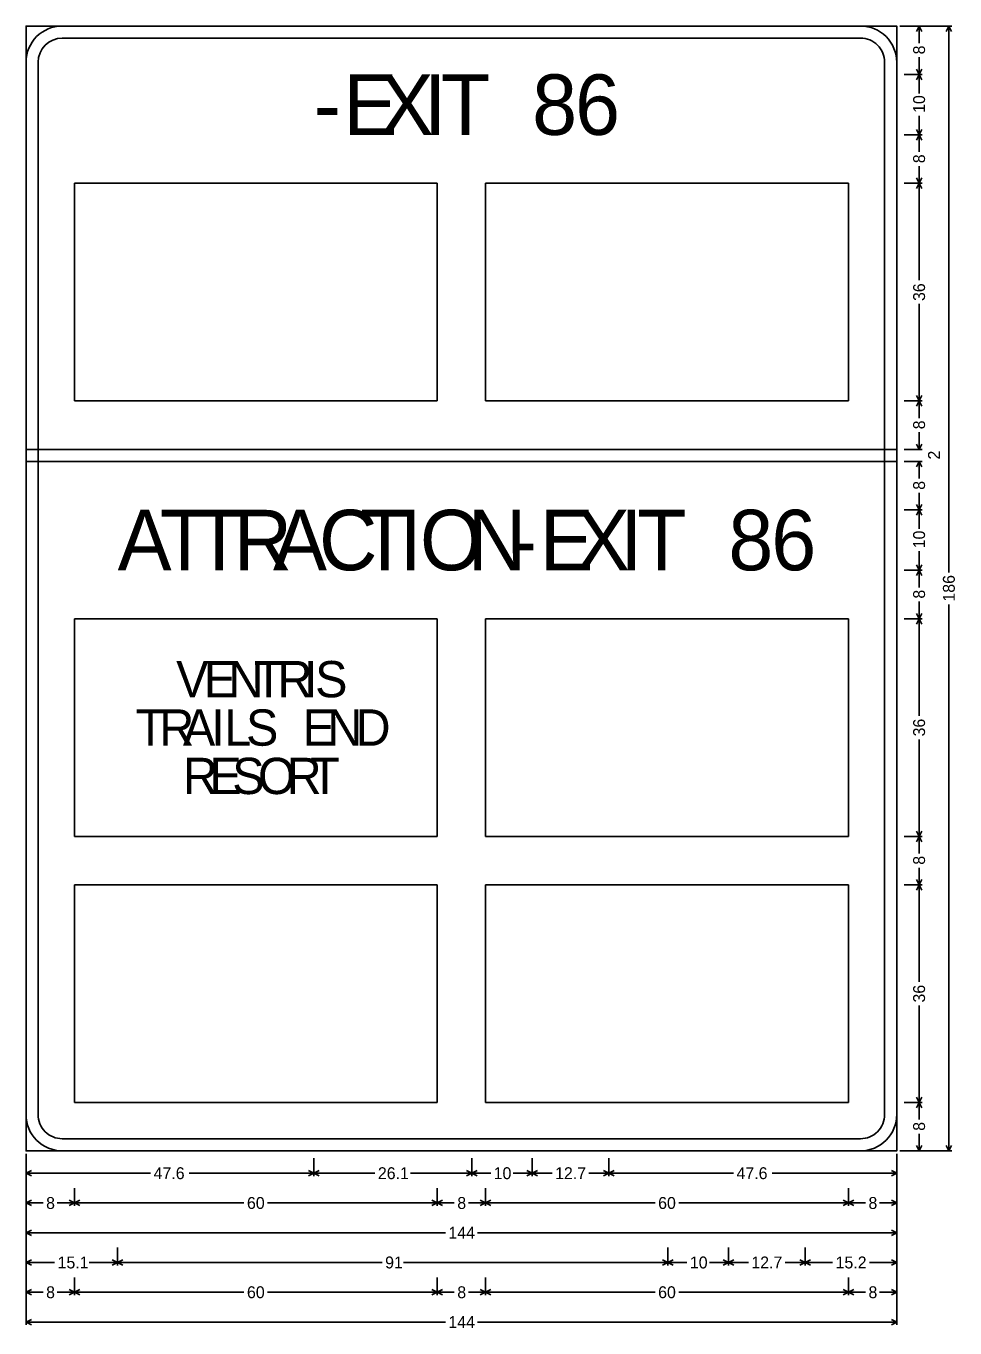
# Model space of a CAD drawing. Extents: x 667331 to 731245, y 738830 to 753817.
# Drawn here: x 729776.8 to 730053.4, y 747199.1 to 747586.6 of the extents above; entities that cross this region are included whole.
import ezdxf

# ---------------------------------------------------------------- set-up
doc = ezdxf.new("R2010")
doc.units = 0
doc.layers.add('R_SIGN', color=7, linetype='Continuous')

msp = doc.modelspace()

# ---------------------------------------------------------------- linework, layer by layer
at = {"layer": 'R_SIGN'}
for p, q in [((730052.43, 747586.65), (730036.93, 747586.65)), ((730043.57, 747586.65), (730038.26, 747586.65)), ((730041.9, 747585.06), (730042.69, 747586.65)), ((730042.69, 747581.56), (730042.69, 747586.65)), ((730043.48, 747585.06), (730042.69, 747586.65)), ((730050.75, 747585.06), (730051.55, 747586.65)), ((730051.55, 747424.04), (730051.55, 747586.65)), ((730052.34, 747585.06), (730051.55, 747586.65)), ((730042.69, 747577.34), (730042.69, 747572.25)), ((730041.9, 747573.83), (730042.69, 747572.25)), ((730043.48, 747573.83), (730042.69, 747572.25)), ((730043.57, 747572.25), (730038.26, 747572.25)), ((730041.9, 747570.66), (730042.69, 747572.25)), ((730042.69, 747566.59), (730042.69, 747572.25)), ((730043.48, 747570.66), (730042.69, 747572.25)), ((730042.69, 747559.9), (730042.69, 747554.25)), ((730043.57, 747554.25), (730038.26, 747554.25)), ((730041.9, 747555.83), (730042.69, 747554.25)), ((730041.9, 747552.66), (730042.69, 747554.25)), ((730043.48, 747555.83), (730042.69, 747554.25)), ((730042.69, 747549.16), (730042.69, 747554.25)), ((730043.48, 747552.66), (730042.69, 747554.25)), ((730041.9, 747541.43), (730042.69, 747539.85)), ((730042.69, 747544.94), (730042.69, 747539.85)), ((730043.48, 747541.43), (730042.69, 747539.85)), ((729791.24, 747475.05), (729791.24, 747539.85)), ((729791.24, 747539.85), (729899.24, 747539.85)), ((729899.24, 747539.85), (729899.24, 747475.05)), ((729913.64, 747475.05), (729913.64, 747539.85)), ((729913.64, 747539.85), (730021.64, 747539.85)), ((730021.64, 747539.85), (730021.64, 747475.05)), ((730043.57, 747539.85), (730038.26, 747539.85)), ((730041.9, 747538.26), (730042.69, 747539.85)), ((730042.69, 747510.98), (730042.69, 747539.85)), ((730043.48, 747538.26), (730042.69, 747539.85)), ((730042.69, 747503.92), (730042.69, 747475.05)), ((730041.9, 747476.63), (730042.69, 747475.05)), ((730043.48, 747476.63), (730042.69, 747475.05)), ((729899.24, 747475.05), (729791.24, 747475.05)), ((730021.64, 747475.05), (729913.64, 747475.05)), ((730043.57, 747475.05), (730038.26, 747475.05)), ((730041.9, 747473.46), (730042.69, 747475.05)), ((730042.69, 747469.96), (730042.69, 747475.05)), ((730043.48, 747473.46), (730042.69, 747475.05)), ((730042.69, 747465.74), (730042.69, 747460.65)), ((730043.57, 747460.65), (730038.26, 747460.65)), ((730041.9, 747462.23), (730042.69, 747460.65)), ((730043.48, 747462.23), (730042.69, 747460.65)), ((730043.57, 747457.05), (730038.26, 747457.05)), ((730041.9, 747455.46), (730042.69, 747457.05)), ((730042.69, 747451.96), (730042.69, 747457.05)), ((730043.48, 747455.46), (730042.69, 747457.05)), ((730042.69, 747447.74), (730042.69, 747442.65)), ((730043.57, 747442.65), (730038.26, 747442.65)), ((730041.9, 747444.23), (730042.69, 747442.65)), ((730041.9, 747441.06), (730042.69, 747442.65)), ((730043.48, 747444.23), (730042.69, 747442.65)), ((730042.69, 747436.99), (730042.69, 747442.65)), ((730043.48, 747441.06), (730042.69, 747442.65)), ((730042.69, 747430.3), (730042.69, 747424.65)), ((730041.9, 747426.23), (730042.69, 747424.65)), ((730043.48, 747426.23), (730042.69, 747424.65)), ((730043.57, 747424.65), (730038.26, 747424.65)), ((730041.9, 747423.06), (730042.69, 747424.65)), ((730042.69, 747419.56), (730042.69, 747424.65)), ((730043.48, 747423.06), (730042.69, 747424.65)), ((730042.69, 747415.34), (730042.69, 747410.25)), ((730051.55, 747414.45), (730051.55, 747251.85)), ((729791.24, 747345.45), (729791.24, 747410.25)), ((729791.24, 747410.25), (729899.24, 747410.25)), ((729899.24, 747410.25), (729899.24, 747345.45)), ((729913.64, 747345.45), (729913.64, 747410.25)), ((729913.64, 747410.25), (730021.64, 747410.25)), ((730021.64, 747410.25), (730021.64, 747345.45)), ((730043.57, 747410.25), (730038.26, 747410.25)), ((730041.9, 747411.83), (730042.69, 747410.25)), ((730041.9, 747408.66), (730042.69, 747410.25)), ((730043.48, 747411.83), (730042.69, 747410.25)), ((730042.69, 747381.38), (730042.69, 747410.25)), ((730043.48, 747408.66), (730042.69, 747410.25)), ((730042.69, 747374.32), (730042.69, 747345.45)), ((729899.24, 747345.45), (729791.24, 747345.45)), ((730021.64, 747345.45), (729913.64, 747345.45)), ((730043.57, 747345.45), (730038.26, 747345.45)), ((730041.9, 747347.03), (730042.69, 747345.45)), ((730041.9, 747343.86), (730042.69, 747345.45)), ((730043.48, 747347.03), (730042.69, 747345.45)), ((730042.69, 747340.36), (730042.69, 747345.45)), ((730043.48, 747343.86), (730042.69, 747345.45)), ((730042.69, 747336.14), (730042.69, 747331.05)), ((730041.9, 747332.63), (730042.69, 747331.05)), ((730043.48, 747332.63), (730042.69, 747331.05)), ((729791.24, 747266.25), (729791.24, 747331.05)), ((729791.24, 747331.05), (729899.24, 747331.05)), ((729899.24, 747331.05), (729899.24, 747266.25)), ((729913.64, 747266.25), (729913.64, 747331.05)), ((729913.64, 747331.05), (730021.64, 747331.05)), ((730021.64, 747331.05), (730021.64, 747266.25)), ((730043.57, 747331.05), (730038.26, 747331.05)), ((730041.9, 747329.46), (730042.69, 747331.05)), ((730042.69, 747302.18), (730042.69, 747331.05)), ((730043.48, 747329.46), (730042.69, 747331.05)), ((730042.69, 747295.12), (730042.69, 747266.25)), ((729899.24, 747266.25), (729791.24, 747266.25)), ((730021.64, 747266.25), (729913.64, 747266.25)), ((730043.57, 747266.25), (730038.26, 747266.25)), ((730043.57, 747266.25), (730038.26, 747266.25)), ((730041.9, 747267.83), (730042.69, 747266.25)), ((730041.9, 747264.66), (730042.69, 747266.25)), ((730043.48, 747267.83), (730042.69, 747266.25)), ((730042.69, 747261.16), (730042.69, 747266.25)), ((730043.48, 747264.66), (730042.69, 747266.25)), ((730042.69, 747256.94), (730042.69, 747251.85)), ((729776.84, 747200.03), (729776.84, 747250.96)), ((730036.04, 747200.03), (730036.04, 747250.96)), ((730052.43, 747251.85), (730036.93, 747251.85)), ((730043.57, 747251.85), (730038.26, 747251.85)), ((730041.9, 747253.43), (730042.69, 747251.85)), ((730043.48, 747253.43), (730042.69, 747251.85)), ((730050.75, 747253.43), (730051.55, 747251.85)), ((730052.34, 747253.43), (730051.55, 747251.85)), ((729776.84, 747244.32), (729776.84, 747249.63)), ((729862.52, 747244.32), (729862.52, 747249.63)), ((729909.5, 747244.32), (729909.5, 747249.63)), ((729927.5, 747244.32), (729927.5, 747249.63)), ((729950.36, 747244.32), (729950.36, 747249.63)), ((729950.36, 747244.32), (729950.36, 747249.63)), ((730036.04, 747244.32), (730036.04, 747249.63)), ((729778.43, 747245.99), (729776.84, 747245.2)), ((729813.94, 747245.2), (729776.84, 747245.2)), ((729778.43, 747244.41), (729776.84, 747245.2)), ((729825.43, 747245.2), (729862.52, 747245.2)), ((729860.94, 747245.99), (729862.52, 747245.2)), ((729860.94, 747244.41), (729862.52, 747245.2)), ((729864.11, 747245.99), (729862.52, 747245.2)), ((729880.7, 747245.2), (729862.52, 747245.2)), ((729864.11, 747244.41), (729862.52, 747245.2)), ((729891.33, 747245.2), (729909.5, 747245.2)), ((729907.92, 747245.99), (729909.5, 747245.2)), ((729907.92, 747244.41), (729909.5, 747245.2)), ((729911.09, 747245.99), (729909.5, 747245.2)), ((729915.16, 747245.2), (729909.5, 747245.2)), ((729911.09, 747244.41), (729909.5, 747245.2)), ((729921.85, 747245.2), (729927.5, 747245.2)), ((729925.92, 747245.99), (729927.5, 747245.2)), ((729925.92, 747244.41), (729927.5, 747245.2)), ((729929.09, 747245.99), (729927.5, 747245.2)), ((729933.46, 747245.2), (729927.5, 747245.2)), ((729929.09, 747244.41), (729927.5, 747245.2)), ((729944.41, 747245.2), (729950.36, 747245.2)), ((729948.78, 747245.99), (729950.36, 747245.2)), ((729948.78, 747244.41), (729950.36, 747245.2)), ((729951.95, 747245.99), (729950.36, 747245.2)), ((729987.46, 747245.2), (729950.36, 747245.2)), ((729951.95, 747244.41), (729950.36, 747245.2)), ((729998.95, 747245.2), (730036.04, 747245.2)), ((730034.46, 747245.99), (730036.04, 747245.2)), ((730034.46, 747244.41), (730036.04, 747245.2)), ((729776.84, 747235.46), (729776.84, 747240.77)), ((729791.24, 747235.46), (729791.24, 747240.77)), ((729899.24, 747235.46), (729899.24, 747240.77)), ((729913.64, 747235.46), (729913.64, 747240.77)), ((730021.64, 747235.46), (730021.64, 747240.77)), ((730021.64, 747235.46), (730021.64, 747240.77)), ((730036.04, 747235.46), (730036.04, 747240.77)), ((729778.43, 747237.14), (729776.84, 747236.34)), ((729781.93, 747236.34), (729776.84, 747236.34)), ((729778.43, 747235.55), (729776.84, 747236.34)), ((729786.15, 747236.34), (729791.24, 747236.34)), ((729789.66, 747237.14), (729791.24, 747236.34)), ((729789.66, 747235.55), (729791.24, 747236.34)), ((729792.83, 747237.14), (729791.24, 747236.34)), ((729841.72, 747236.34), (729791.24, 747236.34)), ((729792.83, 747235.55), (729791.24, 747236.34)), ((729848.77, 747236.34), (729899.24, 747236.34)), ((729897.66, 747237.14), (729899.24, 747236.34)), ((729897.66, 747235.55), (729899.24, 747236.34)), ((729900.83, 747237.14), (729899.24, 747236.34)), ((729904.33, 747236.34), (729899.24, 747236.34)), ((729900.83, 747235.55), (729899.24, 747236.34)), ((729908.55, 747236.34), (729913.64, 747236.34)), ((729912.06, 747237.14), (729913.64, 747236.34)), ((729912.06, 747235.55), (729913.64, 747236.34)), ((729915.23, 747237.14), (729913.64, 747236.34)), ((729964.12, 747236.34), (729913.64, 747236.34)), ((729915.23, 747235.55), (729913.64, 747236.34)), ((729971.17, 747236.34), (730021.64, 747236.34)), ((730020.06, 747237.14), (730021.64, 747236.34)), ((730020.06, 747235.55), (730021.64, 747236.34)), ((730023.23, 747237.14), (730021.64, 747236.34)), ((730026.73, 747236.34), (730021.64, 747236.34)), ((730023.23, 747235.55), (730021.64, 747236.34)), ((730030.95, 747236.34), (730036.04, 747236.34)), ((730034.46, 747237.14), (730036.04, 747236.34)), ((730034.46, 747235.55), (730036.04, 747236.34)), ((729776.84, 747226.6), (729776.84, 747231.91)), ((730036.04, 747226.6), (730036.04, 747231.91)), ((729778.43, 747228.28), (729776.84, 747227.49)), ((729901.69, 747227.49), (729776.84, 747227.49)), ((729778.43, 747226.69), (729776.84, 747227.49)), ((729911.2, 747227.49), (730036.04, 747227.49)), ((730034.46, 747228.28), (730036.04, 747227.49)), ((730034.46, 747226.69), (730036.04, 747227.49)), ((729776.84, 747217.74), (729776.84, 747223.06)), ((729804.11, 747217.74), (729804.11, 747223.06)), ((729967.91, 747217.74), (729967.91, 747223.06)), ((729985.91, 747217.74), (729985.91, 747223.06)), ((730008.77, 747217.74), (730008.77, 747223.06)), ((730008.77, 747217.74), (730008.77, 747223.06)), ((730036.04, 747217.74), (730036.04, 747223.06)), ((729778.43, 747219.42), (729776.84, 747218.63)), ((729785.35, 747218.63), (729776.84, 747218.63)), ((729778.43, 747217.83), (729776.84, 747218.63)), ((729795.6, 747218.63), (729804.11, 747218.63)), ((729802.53, 747219.42), (729804.11, 747218.63)), ((729802.53, 747217.83), (729804.11, 747218.63)), ((729805.7, 747219.42), (729804.11, 747218.63)), ((729882.86, 747218.63), (729804.11, 747218.63)), ((729805.7, 747217.83), (729804.11, 747218.63)), ((729889.17, 747218.63), (729967.91, 747218.63)), ((729966.33, 747219.42), (729967.91, 747218.63)), ((729966.33, 747217.83), (729967.91, 747218.63)), ((729969.5, 747219.42), (729967.91, 747218.63)), ((729973.57, 747218.63), (729967.91, 747218.63)), ((729969.5, 747217.83), (729967.91, 747218.63)), ((729980.26, 747218.63), (729985.91, 747218.63)), ((729984.33, 747219.42), (729985.91, 747218.63)), ((729984.33, 747217.83), (729985.91, 747218.63)), ((729987.5, 747219.42), (729985.91, 747218.63)), ((729991.87, 747218.63), (729985.91, 747218.63)), ((729987.5, 747217.83), (729985.91, 747218.63)), ((730002.82, 747218.63), (730008.77, 747218.63)), ((730007.19, 747219.42), (730008.77, 747218.63)), ((730007.19, 747217.83), (730008.77, 747218.63)), ((730010.36, 747219.42), (730008.77, 747218.63)), ((730016.94, 747218.63), (730008.77, 747218.63)), ((730010.36, 747217.83), (730008.77, 747218.63)), ((730027.88, 747218.63), (730036.04, 747218.63)), ((730034.46, 747219.42), (730036.04, 747218.63)), ((730034.46, 747217.83), (730036.04, 747218.63)), ((729776.84, 747208.88), (729776.84, 747214.2)), ((729791.24, 747208.88), (729791.24, 747214.2)), ((729899.24, 747208.88), (729899.24, 747214.2)), ((729913.64, 747208.88), (729913.64, 747214.2)), ((730021.64, 747208.88), (730021.64, 747214.2)), ((730021.64, 747208.88), (730021.64, 747214.2)), ((730036.04, 747208.88), (730036.04, 747214.2)), ((729778.43, 747210.56), (729776.84, 747209.77)), ((729781.93, 747209.77), (729776.84, 747209.77)), ((729778.43, 747208.98), (729776.84, 747209.77)), ((729786.15, 747209.77), (729791.24, 747209.77)), ((729789.66, 747210.56), (729791.24, 747209.77)), ((729789.66, 747208.98), (729791.24, 747209.77)), ((729792.83, 747210.56), (729791.24, 747209.77)), ((729841.72, 747209.77), (729791.24, 747209.77)), ((729792.83, 747208.98), (729791.24, 747209.77)), ((729848.77, 747209.77), (729899.24, 747209.77)), ((729897.66, 747210.56), (729899.24, 747209.77)), ((729897.66, 747208.98), (729899.24, 747209.77)), ((729900.83, 747210.56), (729899.24, 747209.77)), ((729904.33, 747209.77), (729899.24, 747209.77)), ((729900.83, 747208.98), (729899.24, 747209.77)), ((729908.55, 747209.77), (729913.64, 747209.77)), ((729912.06, 747210.56), (729913.64, 747209.77)), ((729912.06, 747208.98), (729913.64, 747209.77)), ((729915.23, 747210.56), (729913.64, 747209.77)), ((729964.12, 747209.77), (729913.64, 747209.77)), ((729915.23, 747208.98), (729913.64, 747209.77)), ((729971.17, 747209.77), (730021.64, 747209.77)), ((730020.06, 747210.56), (730021.64, 747209.77)), ((730020.06, 747208.98), (730021.64, 747209.77)), ((730023.23, 747210.56), (730021.64, 747209.77)), ((730026.73, 747209.77), (730021.64, 747209.77)), ((730023.23, 747208.98), (730021.64, 747209.77)), ((730030.95, 747209.77), (730036.04, 747209.77)), ((730034.46, 747210.56), (730036.04, 747209.77)), ((730034.46, 747208.98), (730036.04, 747209.77)), ((729778.43, 747201.7), (729776.84, 747200.91)), ((729901.69, 747200.91), (729776.84, 747200.91)), ((729778.43, 747200.12), (729776.84, 747200.91)), ((729911.2, 747200.91), (730036.04, 747200.91)), ((730034.46, 747201.7), (730036.04, 747200.91)), ((730034.46, 747200.12), (730036.04, 747200.91))]:
    msp.add_line(p, q, dxfattribs=at)
for points in [[(729776.84, 747251.85), (730036.04, 747251.85), (730036.04, 747586.65), (729776.84, 747586.65), (729776.84, 747251.85), (729776.84, 747251.85)], [(729787.64, 747586.65), (730025.24, 747586.65)], [(730025.24, 747583.05), (729787.64, 747583.05)], [(729776.84, 747262.65), (729776.84, 747575.85)], [(729780.44, 747575.85), (729780.44, 747262.65)], [(730032.44, 747262.65), (730032.44, 747575.85)], [(730036.04, 747575.85), (730036.04, 747262.65)], [(730036.04, 747457.05), (729776.84, 747457.05), (729776.84, 747460.65), (730036.04, 747460.65), (730036.04, 747457.05), (730036.04, 747457.05)], [(729787.64, 747255.45), (730025.24, 747255.45)], [(730025.24, 747251.85), (729787.64, 747251.85)]]:
    msp.add_lwpolyline(points, dxfattribs=at)
for centre, radius, start, end in [((729787.64, 747575.85), 10.8, 90.0002, 179.9998), ((730025.24, 747575.85), 10.8, 0, 90.0002), ((729787.64, 747575.85), 7.2, 90.0002, 179.9998), ((730025.24, 747575.85), 7.2, 0, 90.0002), ((729787.64, 747262.65), 10.8, 179.9998, 270.0001), ((729787.64, 747262.65), 7.2, 179.9998, 270.0001), ((730025.24, 747262.65), 10.8, 270.0001, 0.0003), ((730025.24, 747262.65), 7.2, 270.0001, 0.0003)]:
    msp.add_arc(centre, radius, start, end, dxfattribs=at)

# ---------------------------------------------------------------- texts
for s, height, p in [('8', 3.54, (730044.46, 747578.22)), ('10', 3.543, (730044.46, 747560.79)), ('8', 3.54, (730044.46, 747545.82)), ('36', 3.543, (730044.46, 747504.8)), ('8', 3.54, (730044.46, 747466.62)), ('2', 3.54, (730048.89, 747457.62)), ('8', 3.54, (730044.46, 747448.62)), ('10', 3.543, (730044.46, 747431.19)), ('186', 3.543, (730053.32, 747415.34)), ('8', 3.54, (730044.46, 747416.22)), ('36', 3.543, (730044.46, 747375.2)), ('8', 3.54, (730044.46, 747337.02)), ('36', 3.543, (730044.46, 747296)), ('8', 3.54, (730044.46, 747257.82))]:
    msp.add_text(s, height=height, rotation=90.0002, dxfattribs=at).set_placement(p)
for s, height, p in [('8', 18, (729927.5, 747554.25)), ('6', 18, (729940.28, 747554.25)), ('E', 18, (729871.34, 747554.25)), ('X', 18, (729882.14, 747554.25)), ('I', 18, (729895.28, 747554.25)), ('T', 18, (729900.32, 747554.25)), ('-', 18, (729862.52, 747554.25)), ('A', 18, (729804.11, 747424.65)), ('T', 18, (729816.71, 747424.65)), ('T', 18, (729826.97, 747424.65)), ('R', 18, (729838.67, 747424.65)), ('A', 18, (729850.37, 747424.65)), ('C', 18, (729864.05, 747424.65)), ('T', 18, (729876.29, 747424.65)), ('I', 18, (729887.99, 747424.65)), ('O', 18, (729894.11, 747424.65)), ('N', 18, (729908.33, 747424.65)), ('E', 18, (729929.75, 747424.65)), ('X', 18, (729940.55, 747424.65)), ('I', 18, (729953.69, 747424.65)), ('T', 18, (729958.73, 747424.65)), ('8', 18, (729985.91, 747424.65)), ('6', 18, (729998.69, 747424.65)), ('-', 18, (729920.93, 747424.65)), ('V', 10.8, (729821.54, 747386.85)), ('E', 10.8, (729829.75, 747386.85)), ('N', 10.8, (729837.09, 747386.85)), ('T', 10.8, (729844.65, 747386.85)), ('R', 10.8, (729851.67, 747386.85)), ('I', 10.8, (729859.55, 747386.85)), ('S', 10.8, (729862.9, 747386.85)), ('T', 10.8, (729809.5, 747372.45)), ('R', 10.8, (729816.52, 747372.45)), ('A', 10.8, (729823.54, 747372.45)), ('I', 10.8, (729831.96, 747372.45)), ('L', 10.8, (729835.85, 747372.45)), ('S', 10.8, (729842.33, 747372.45)), ('E', 10.8, (729859.18, 747372.45)), ('N', 10.8, (729866.52, 747372.45)), ('D', 10.8, (729874.94, 747372.45)), ('R', 10.8, (729823.54, 747358.05)), ('E', 10.8, (729831.42, 747358.05)), ('S', 10.8, (729838.22, 747358.05)), ('O', 10.8, (729845.89, 747358.05)), ('R', 10.8, (729854.42, 747358.05)), ('T', 10.8, (729861.44, 747358.05)), ('47.6', 3.543, (729814.82, 747243.43)), ('26.1', 3.543, (729881.58, 747243.43)), ('10', 3.543, (729916.05, 747243.43)), ('12.7', 3.543, (729934.34, 747243.43)), ('47.6', 3.543, (729988.34, 747243.43)), ('8', 3.54, (729782.82, 747234.57)), ('60', 3.543, (729842.61, 747234.57)), ('8', 3.54, (729905.22, 747234.57)), ('60', 3.543, (729965.01, 747234.57)), ('8', 3.54, (730027.62, 747234.57)), ('144', 3.543, (729902.58, 747225.71)), ('15.1', 3.543, (729786.24, 747216.86)), ('91', 3.543, (729883.74, 747216.86)), ('10', 3.543, (729974.46, 747216.86)), ('12.7', 3.543, (729992.75, 747216.86)), ('15.2', 3.543, (730017.83, 747216.86)), ('8', 3.54, (729782.82, 747208)), ('60', 3.543, (729842.61, 747208)), ('8', 3.54, (729905.22, 747208)), ('60', 3.543, (729965.01, 747208)), ('8', 3.54, (730027.62, 747208)), ('144', 3.543, (729902.58, 747199.14))]:
    msp.add_text(s, height=height, dxfattribs=at).set_placement(p)

doc.saveas('drawing.dxf')
